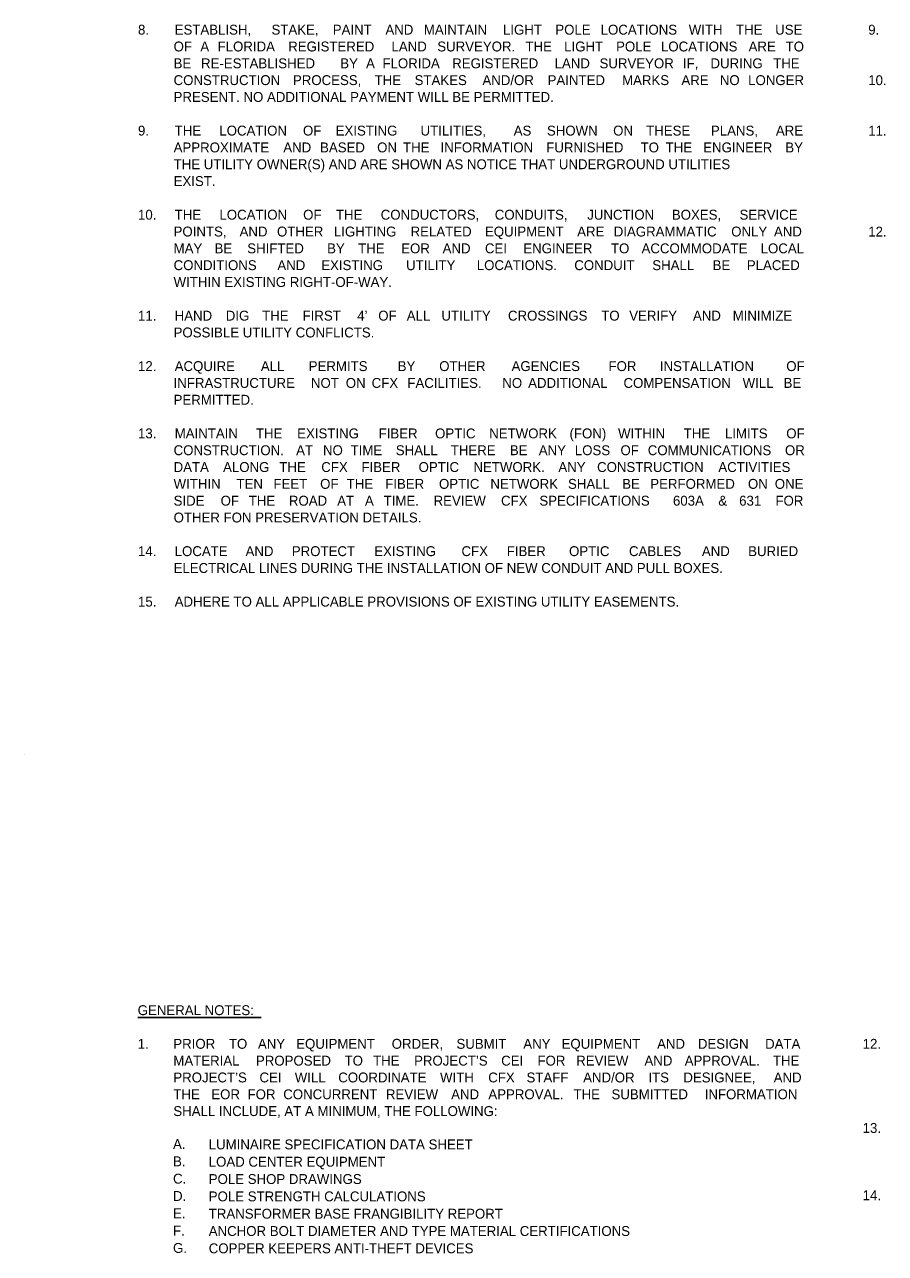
# Model space of a CAD drawing. Extents: x -55 to 2471539, y -90 to 3608906.
# Drawn here: x -54 to 555, y 780 to 1649 of the extents above; entities that cross this region are included whole.
import ezdxf

# ---------------------------------------------------------------- set-up
doc = ezdxf.new("R2010")
doc.units = 0
doc.layers.add('TextMinor', color=7, linetype='Continuous')
doc.layers.add('XSCell', color=7, linetype='Continuous')

msp = doc.modelspace()

# ---------------------------------------------------------------- linework, layer by layer
at = {"layer": 'TextMinor'}
msp.add_line((-54.3, 1133.16), (-54.3, 1133.16), dxfattribs=at)
at = {"layer": 'XSCell'}
msp.add_line((25.73, 946.96), (113.02, 946.96), dxfattribs=at)

# ---------------------------------------------------------------- texts
for s, p in [('8.', (25.93, 1642.28)), ('ESTABLISH, ', (51.88, 1642.28)), ('STAKE, ', (120.37, 1642.28)), ('PAINT ', (163.7, 1642.28)), ('AND ', (200.95, 1642.28)), ('MAINTAIN ', (228.11, 1642.28)), ('LIGHT ', (284.09, 1642.28)), ('POLE ', (321.15, 1642.28)), ('LOCATIONS ', (353.19, 1642.28)), ('WITH ', (415.49, 1642.28)), ('THE ', (448.94, 1642.28)), ('USE ', (476.64, 1642.28)), ('9.', (542.46, 1642.24)), ('OF ', (51.12, 1630.38)), ('A ', (70.02, 1630.38)), ('FLORIDA ', (82.24, 1630.38)), ('REGISTERED ', (132.19, 1630.38)), ('LAND ', (205.23, 1630.38)), ('SURVEYOR. ', (237.62, 1630.38)), ('THE ', (299.99, 1630.38)), ('LIGHT ', (327.38, 1630.38)), ('POLE ', (364.11, 1630.38)), ('LOCATIONS ', (395.84, 1630.38)), ('ARE ', (457.83, 1630.38)), ('TO ', (484.06, 1630.38)), ('RE-ESTABLISHED ', (70.53, 1618.48)), ('FLORIDA ', (198.84, 1618.48)), ('REGISTERED ', (248.18, 1618.48)), ('SURVEYOR ', (352.39, 1618.48)), ('DURING ', (430.89, 1618.48)), ('BE ', (51.12, 1618.48)), ('BY ', (169.03, 1618.48)), ('A ', (187.23, 1618.48)), ('LAND ', (320.61, 1618.48)), ('IF, ', (411.39, 1618.48)), ('THE ', (475.23, 1618.48)), ('CONSTRUCTION ', (51.12, 1606.58)), ('PROCESS, ', (135.53, 1606.58)), ('THE ', (193.29, 1606.58)), ('STAKES ', (221.6, 1606.58)), ('AND/OR ', (269.57, 1606.58)), ('PAINTED ', (315.68, 1606.58)), ('MARKS ', (368.35, 1606.58)), ('ARE ', (410.33, 1606.58)), ('NO ', (437.49, 1606.58)), ('LONGER ', (457.53, 1606.58)), ('10.', (542.46, 1606.54)), ('PRESENT. NO ADDITIONAL PAYMENT WILL BE PERMITTED.', (51.12, 1594.68)), ('9.', (25.93, 1570.88)), ('THE ', (51.88, 1570.88)), ('LOCATION ', (83.48, 1570.88)), ('OF ', (142.62, 1570.88)), ('EXISTING ', (165.74, 1570.88)), ('UTILITIES, ', (225.78, 1570.88)), ('AS ', (291.68, 1570.88)), ('SHOWN ', (315.2, 1570.88)), ('ON ', (362.04, 1570.88)), ('THESE ', (385.38, 1570.88)), ('PLANS, ', (431.2, 1570.88)), ('ARE ', (477.14, 1570.88)), ('11.', (542.46, 1570.84)), ('APPROXIMATE ', (51.12, 1558.98)), ('AND ', (128.7, 1558.98)), ('BASED ', (154.72, 1558.98)), ('ON ', (195.09, 1558.98)), ('THE ', (213.38, 1558.98)), ('INFORMATION ', (239.94, 1558.98)), ('FURNISHED ', (314.71, 1558.98)), ('TO ', (381.43, 1558.98)), ('THE ', (399.16, 1558.98)), ('ENGINEER ', (425.72, 1558.98)), ('BY ', (483.8, 1558.98)), ('THE UTILITY OWNER(S) AND ARE SHOWN AS NOTICE THAT UNDERGROUND UTILITIES ', (51.12, 1547.08)), ('EXIST.', (51.12, 1535.18)), ('10.', (25.93, 1511.38)), ('THE ', (51.88, 1511.38)), ('LOCATION ', (83.55, 1511.38)), ('OF ', (142.75, 1511.38)), ('THE ', (165.94, 1511.38)), ('CONDUCTORS, ', (197.62, 1511.38)), ('CONDUITS, ', (278.3, 1511.38)), ('JUNCTION ', (343.7, 1511.38)), ('BOXES, ', (403.57, 1511.38)), ('SERVICE ', (451.42, 1511.38)), ('POINTS, ', (51.12, 1499.48)), ('AND ', (97.78, 1499.48)), ('OTHER ', (124.25, 1499.48)), ('LIGHTING ', (164.51, 1499.48)), ('RELATED ', (218.76, 1499.48)), ('EQUIPMENT ', (271.36, 1499.48)), ('ARE ', (336.58, 1499.48)), ('DIAGRAMMATIC ', (362.44, 1499.48)), ('ONLY ', (445.54, 1499.48)), ('AND ', (475.77, 1499.48)), ('12.', (542.46, 1499.44)), ('MAY ', (51.12, 1487.58)), ('BE ', (80.1, 1487.58)), ('SHIFTED ', (103.22, 1487.58)), ('BY ', (159.71, 1487.58)), ('THE ', (181.63, 1487.58)), ('EOR ', (212.11, 1487.58)), ('AND ', (241.4, 1487.58)), ('CEI ', (271.34, 1487.58)), ('ENGINEER ', (298.47, 1487.58)), ('TO ', (360.47, 1487.58)), ('ACCOMMODATE ', (382.12, 1487.58)), ('LOCAL ', (466.36, 1487.58)), ('CONDITIONS ', (51.12, 1475.68)), ('AND ', (124.51, 1475.68)), ('EXISTING ', (155.55, 1475.68)), ('UTILITY ', (215.58, 1475.68)), ('LOCATIONS. ', (265.58, 1475.68)), ('CONDUIT ', (334.53, 1475.68)), ('SHALL ', (389.71, 1475.68)), ('BE ', (432.37, 1475.68)), ('PLACED ', (456.59, 1475.68)), ('WITHIN EXISTING RIGHT-OF-WAY.', (51.12, 1463.78)), ('11.', (25.93, 1439.98)), ('HAND ', (51.88, 1439.98)), ('DIG ', (88.04, 1439.98)), ('THE ', (113.72, 1439.98)), ('FIRST ', (142.35, 1439.98)), ('4’ ', (180.98, 1439.98)), ('OF ', (195.88, 1439.98)), ('ALL ', (216.02, 1439.98)), ('UTILITY ', (240.58, 1439.98)), ('CROSSINGS ', (287.63, 1439.98)), ('TO ', (353.61, 1439.98)), ('VERIFY ', (373.41, 1439.98)), ('AND ', (418.48, 1439.98)), ('MINIMIZE ', (446.58, 1439.98)), ('POSSIBLE UTILITY CONFLICTS.', (51.12, 1428.08)), ('12.', (25.93, 1404.28)), ('ACQUIRE ', (51.88, 1404.28)), ('ALL ', (112.83, 1404.28)), ('PERMITS ', (146.69, 1404.28)), ('BY ', (209.63, 1404.28)), ('OTHER ', (239, 1404.28)), ('AGENCIES ', (290.18, 1404.28)), ('FOR ', (358.74, 1404.28)), ('INSTALLATION ', (395.06, 1404.28)), ('OF ', (484.48, 1404.28)), ('INFRASTRUCTURE ', (51.12, 1392.38)), ('NOT ', (148.26, 1392.38)), ('ON ', (172.92, 1392.38)), ('CFX ', (191.2, 1392.38)), ('FACILITIES. ', (216.47, 1392.38)), ('NO ', (283.62, 1392.38)), ('ADDITIONAL ', (301.9, 1392.38)), ('COMPENSATION ', (369.37, 1392.38)), ('WILL ', (453.64, 1392.38)), ('BE ', (482.6, 1392.38)), ('PERMITTED.', (51.12, 1380.48)), ('13.', (25.93, 1356.68)), ('MAINTAIN ', (51.88, 1356.68)), ('THE ', (109.34, 1356.68)), ('EXISTING ', (138.52, 1356.68)), ('FIBER ', (196.14, 1356.68)), ('OPTIC ', (236.08, 1356.68)), ('NETWORK ', (274.38, 1356.68)), ('(FON) ', (331.18, 1356.68)), ('WITHIN ', (365.51, 1356.68)), ('THE ', (411.91, 1356.68)), ('LIMITS ', (441.09, 1356.68)), ('OF ', (484.48, 1356.68)), ('CONSTRUCTION. ', (51.12, 1344.78)), ('AT ', (137.78, 1344.78)), ('NO ', (156.79, 1344.78)), ('TIME ', (176.31, 1344.78)), ('SHALL ', (208.3, 1344.78)), ('THERE ', (247.17, 1344.78)), ('BE ', (288.98, 1344.78)), ('ANY ', (309.41, 1344.78)), ('LOSS ', (334.92, 1344.78)), ('OF ', (367.21, 1344.78)), ('COMMUNICATIONS ', (386.52, 1344.78)), ('OR ', (483.56, 1344.78)), ('DATA ', (51.12, 1332.88)), ('ALONG ', (86.11, 1332.88)), ('THE ', (125.89, 1332.88)), ('CFX ', (155.57, 1332.88)), ('FIBER ', (183.98, 1332.88)), ('OPTIC ', (224.42, 1332.88)), ('NETWORK. ', (263.22, 1332.88)), ('ANY ', (323.28, 1332.88)), ('CONSTRUCTION ', (350.66, 1332.88)), ('ACTIVITIES ', (436.44, 1332.88)), ('WITHIN ', (51.12, 1320.98)), ('TEN ', (95.6, 1320.98)), ('FEET ', (121.73, 1320.98)), ('OF ', (154.77, 1320.98)), ('THE ', (173.54, 1320.98)), ('FIBER ', (200.8, 1320.98)), ('OPTIC ', (238.82, 1320.98)), ('NETWORK ', (275.2, 1320.98)), ('SHALL ', (330.08, 1320.98)), ('BE ', (368.42, 1320.98)), ('PERFORMED ', (388.31, 1320.98)), ('ON ', (457.38, 1320.98)), ('ONE ', (476.37, 1320.98)), ('SIDE ', (51.12, 1309.08)), ('OF ', (84.37, 1309.08)), ('THE ', (104.28, 1309.08)), ('ROAD ', (132.68, 1309.08)), ('AT ', (166.85, 1309.08)), ('A ', (186.46, 1309.08)), ('TIME. ', (199.69, 1309.08)), ('REVIEW ', (235.03, 1309.08)), ('CFX ', (282.72, 1309.08)), ('SPECIFICATIONS ', (309.84, 1309.08)), ('603A ', (404.34, 1309.08)), ('& ', (436.43, 1309.08)), ('631 ', (451.16, 1309.08)), ('FOR ', (476.84, 1309.08)), ('OTHER FON PRESERVATION DETAILS.', (51.12, 1297.18)), ('14.', (25.93, 1273.38)), ('LOCATE ', (51.88, 1273.38)), ('AND ', (102, 1273.38)), ('PROTECT ', (134.75, 1273.38)), ('EXISTING ', (193.03, 1273.38)), ('CFX ', (254.76, 1273.38)), ('FIBER ', (286.78, 1273.38)), ('OPTIC ', (330.84, 1273.38)), ('CABLES ', (373.25, 1273.38)), ('AND ', (424.79, 1273.38)), ('BURIED ', (457.54, 1273.38)), ('ELECTRICAL LINES DURING THE INSTALLATION OF NEW CONDUIT AND PULL BOXES.', (51.12, 1261.48)), ('15.', (25.93, 1237.68)), ('ADHERE TO ALL APPLICABLE PROVISIONS OF EXISTING UTILITY EASEMENTS.', (51.88, 1237.68)), ('GENERAL NOTES:', (25.72, 948.68)), ('1.', (25.72, 924.88)), ('PRIOR ', (50.92, 924.88)), ('TO ', (90.22, 924.88)), ('ANY ', (110.76, 924.88)), ('EQUIPMENT ', (137.83, 924.88)), ('ORDER, ', (205.4, 924.88)), ('SUBMIT ', (251.19, 924.88)), ('ANY ', (298.48, 924.88)), ('EQUIPMENT ', (325.55, 924.88)), ('AND ', (393.12, 924.88)), ('DESIGN ', (421.95, 924.88)), ('DATA ', (469.51, 924.88)), ('12.', (538.51, 924.88)), ('MATERIAL ', (50.92, 912.98)), ('PROPOSED ', (109.37, 912.98)), ('TO ', (172.05, 912.98)), ('THE ', (192.22, 912.98)), ('PROJECT’S ', (221.23, 912.98)), ('CEI ', (282.84, 912.98)), ('FOR ', (308.49, 912.98)), ('REVIEW ', (335.89, 912.98)), ('AND ', (384.18, 912.98)), ('APPROVAL. ', (412.65, 912.98)), ('THE ', (475.03, 912.98)), ('PROJECT’S ', (50.92, 901.08)), ('CEI ', (111.85, 901.08)), ('WILL ', (136.83, 901.08)), ('COORDINATE ', (167.58, 901.08)), ('WITH ', (239.59, 901.08)), ('CFX ', (273.68, 901.08)), ('STAFF ', (300.75, 901.08)), ('AND/OR ', (340.81, 901.08)), ('ITS ', (386.95, 901.08)), ('DESIGNEE, ', (411.69, 901.08)), ('AND ', (475.56, 901.08)), ('THE ', (50.92, 889.18)), ('EOR ', (77.78, 889.18)), ('FOR ', (103.44, 889.18)), ('CONCURRENT ', (128.68, 889.18)), ('REVIEW ', (201.3, 889.18)), ('AND ', (247.45, 889.18)), ('APPROVAL. ', (273.76, 889.18)), ('THE ', (333.99, 889.18)), ('SUBMITTED ', (360.85, 889.18)), ('INFORMATION ', (426.82, 889.18)), ('SHALL INCLUDE, AT A MINIMUM, THE FOLLOWING:', (50.92, 877.28)), ('13.', (538.51, 865.38)), ('A.', (50.72, 853.98)), ('LUMINAIRE SPECIFICATION DATA SHEET', (75.97, 853.71)), ('B.', (50.72, 841.73)), ('LOAD CENTER EQUIPMENT', (75.97, 841.46)), ('C.', (50.72, 829.48)), ('POLE SHOP DRAWINGS', (75.97, 829.21)), ('D.', (50.72, 817.23)), ('POLE STRENGTH CALCULATIONS', (75.97, 816.96)), ('14.', (538.51, 817.78)), ('E.', (50.72, 804.98)), ('TRANSFORMER BASE FRANGIBILITY REPORT', (75.97, 804.71)), ('F.', (50.72, 792.73)), ('ANCHOR BOLT DIAMETER AND TYPE MATERIAL CERTIFICATIONS', (75.97, 792.46)), ('G.', (50.72, 780.48)), ('COPPER KEEPERS ANTI-THEFT DEVICES', (75.97, 780.21))]:
    msp.add_text(s, height=7, dxfattribs=at).set_placement(p)

doc.saveas('drawing.dxf')
